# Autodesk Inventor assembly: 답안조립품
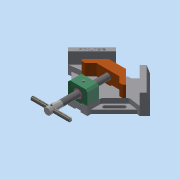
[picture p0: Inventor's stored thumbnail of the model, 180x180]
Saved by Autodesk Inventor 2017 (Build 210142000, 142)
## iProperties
Part Number: 답안조립품
Material: 일반
Document SubType Name: Assembly
Designer: mrc
Author: mrc
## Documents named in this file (11)
- C:\Users\mrc\Desktop\700506V1011\답안조립품.iam
- C:\Users\mrc\Desktop\700506V1011\본체.ipt
- C:\Users\mrc\Desktop\700506V1011\리드스크류.ipt
- C:\Users\mrc\Desktop\700506V1011\멈춤나사 M4x5.ipt
- C:\Users\mrc\Desktop\700506V1011\멈춤나사 M4x10.ipt
- C:\Users\mrc\Desktop\700506V1011\볼트 M4x16.ipt
- C:\Users\mrc\Desktop\700506V1011\부시.ipt
- C:\Users\mrc\Desktop\700506V1011\서포트.ipt
- C:\Users\mrc\Desktop\700506V1011\조.ipt
- C:\Users\mrc\Desktop\700506V1011\평행 핀 2.5x24.ipt
- C:\Users\mrc\Desktop\700506V1011\핸들.ipt
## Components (1 placed, 1 different names)
1. 핸들:1
